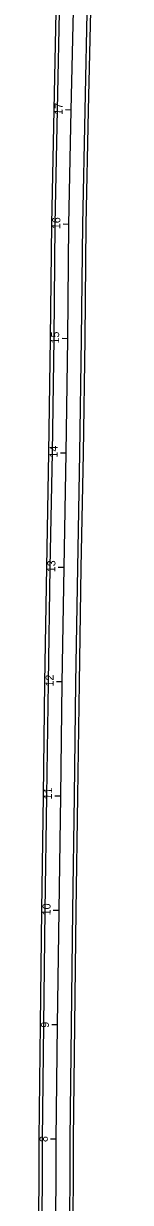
# Model space of a CAD drawing. Extents: x 2318076 to 2324211, y 613525 to 629939.
# Drawn here: x 2318871 to 2318937, y 615680 to 616711 of the extents above; entities that cross this region are included whole.
import ezdxf

# ---------------------------------------------------------------- set-up
doc = ezdxf.new("R2010")
doc.units = 0
for name, color, linetype in [('GE_P_CL_50', 7, 'Continuous'), ('PV_P_EOP', 7, 'Continuous'), ('PV_P_Shoulder', 7, 'Continuous')]:
    doc.layers.add(name, color=color, linetype=linetype)

msp = doc.modelspace()

# ---------------------------------------------------------------- linework, layer by layer
at = {"layer": 'GE_P_CL_50'}
for p, q in [((2318899.2, 616635.4), (2318894.2, 616635.5)), ((2318897.2, 616535.4), (2318892.2, 616535.5)), ((2318896.2, 616435.4), (2318891.2, 616435.5)), ((2318894.8, 616335.4), (2318889.8, 616335.5)), ((2318892.9, 616235.4), (2318887.9, 616235.5)), ((2318891.3, 616135.5), (2318886.3, 616135.5)), ((2318890, 616035.5), (2318885, 616035.5)), ((2318888.6, 615935.5), (2318883.6, 615935.6)), ((2318887.3, 615835.5), (2318882.3, 615835.5)), ((2318886.2, 615735.5), (2318881.2, 615735.6))]:
    msp.add_line(p, q, dxfattribs=at)
msp.add_lwpolyline([(2318885.9, 615635.5), (2318886.2, 615735.5), (2318887.3, 615835.5), (2318888.6, 615935.5), (2318890, 616035.5), (2318891.3, 616134.6), (2318892.9, 616235.4), (2318894.8, 616335.4), (2318896.2, 616435.4), (2318897.2, 616535.4), (2318899.2, 616635.4), (2318901.4, 616735.4), (2318903.1, 616835.4), (2318904.5, 616935.3), (2318906.2, 617035.3), (2318907.6, 617135.3), (2318909.8, 617235.3), (2318911.9, 617335.3), (2318913.9, 617435.2), (2318914.6, 617477.3), (2318915.8, 617533.4), (2318918, 617635.2), (2318920.2, 617734.2), (2318922.5, 617835.2)], dxfattribs=at)
at = {"layer": 'PV_P_EOP'}
for points in [[(2318873.9, 615635.6), (2318874.2, 615735.6), (2318875.3, 615835.6), (2318876.6, 615935.6), (2318878, 616035.6), (2318879.3, 616134.8), (2318880.9, 616235.7), (2318882.8, 616335.6), (2318884.2, 616435.6), (2318885.2, 616535.6), (2318887.2, 616635.6), (2318889.4, 616735.6), (2318891.1, 616835.5), (2318892.5, 616935.5), (2318894.2, 617035.5), (2318895.6, 617135.5), (2318897.8, 617235.5), (2318899.9, 617335.5), (2318902, 617435.5), (2318902.6, 617477.5), (2318903.8, 617533.7), (2318906, 617635.5), (2318908.2, 617734.5), (2318910.5, 617835.4)], [(2318897.9, 615635.4), (2318898.2, 615735.4), (2318899.3, 615835.3), (2318900.6, 615935.3), (2318902, 616035.3), (2318903.3, 616134.4), (2318904.8, 616235.2), (2318906.8, 616335.2), (2318908.2, 616435.3), (2318909.2, 616535.2), (2318911.2, 616635.1), (2318913.4, 616735.1), (2318915.1, 616835.2), (2318916.5, 616935.2), (2318918.2, 617035.1), (2318919.6, 617135.1), (2318921.8, 617235), (2318923.9, 617335), (2318925.9, 617435), (2318926.6, 617477), (2318927.8, 617533.2), (2318930, 617634.9), (2318932.2, 617733.9), (2318934.5, 617834.9)]]:
    msp.add_lwpolyline(points, dxfattribs=at)
at = {"layer": 'PV_P_Shoulder'}
for points in [[(2318870.9, 615635.6), (2318871.2, 615735.6), (2318872.3, 615835.7), (2318873.6, 615935.7), (2318875, 616035.7), (2318876.3, 616134.8), (2318877.9, 616235.7), (2318879.8, 616335.7), (2318881.2, 616435.6), (2318882.2, 616535.6), (2318884.2, 616635.7), (2318886.4, 616735.7), (2318888.1, 616835.6), (2318889.5, 616935.6), (2318891.2, 617035.6), (2318892.6, 617135.6), (2318894.8, 617235.6), (2318896.9, 617335.6), (2318899, 617435.5), (2318899.6, 617477.6), (2318900.8, 617533.7), (2318903, 617635.5), (2318905.2, 617734.5), (2318907.5, 617835.5)], [(2318900.9, 615635.4), (2318901.2, 615735.4), (2318902.3, 615835.3), (2318903.6, 615935.3), (2318905, 616035.3), (2318906.3, 616134.4), (2318907.8, 616235.2), (2318909.8, 616335.2), (2318911.2, 616435.2), (2318912.2, 616535.2), (2318914.2, 616635.1), (2318916.4, 616735.1), (2318918.1, 616835.1), (2318919.5, 616935.1), (2318921.2, 617035.1), (2318922.6, 617135), (2318924.8, 617235), (2318926.9, 617335), (2318928.9, 617435), (2318929.6, 617477), (2318930.8, 617533.1), (2318933, 617634.9), (2318935.2, 617733.9), (2318937.5, 617834.8)]]:
    msp.add_lwpolyline(points, dxfattribs=at)

# ---------------------------------------------------------------- texts
at = {"layer": 'GE_P_CL_50'}
for s, rotation, p in [('17', 88.5663, (2318891.6, 616631.1)), ('16', 89.2594, (2318889.6, 616531.2)), ('15', 89.5566, (2318888.6, 616431.2)), ('14', 88.6506, (2318887.2, 616331.4)), ('13', 89.0608, (2318885.3, 616231.2)), ('12', 89.4127, (2318883.8, 616131.3)), ('11', 89.099, (2318882.4, 616032.5)), ('10', 89.0912, (2318881.1, 615931.2)), ('9', 89.5258, (2318879.8, 615832.9)), ('8', 89.3066, (2318878.7, 615733))]:
    msp.add_text(s, height=7, rotation=rotation, dxfattribs=at).set_placement(p)

doc.saveas('drawing.dxf')
